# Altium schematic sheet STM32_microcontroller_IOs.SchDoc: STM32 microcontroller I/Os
size A4; Date: Not used; ApprovedBy: Not used; CheckedBy: Not used; Author: Not used; CompanyName: STMicroelectronics; DrawnBy: Not used; Engineer: Not used; Organization: Not used; Address1: Not used; Address2: Not used; Address3: Not used; Address4: Not used; DocumentNumber: 3; Revision: Not used; SheetNumber: 3; SheetTotal: 8
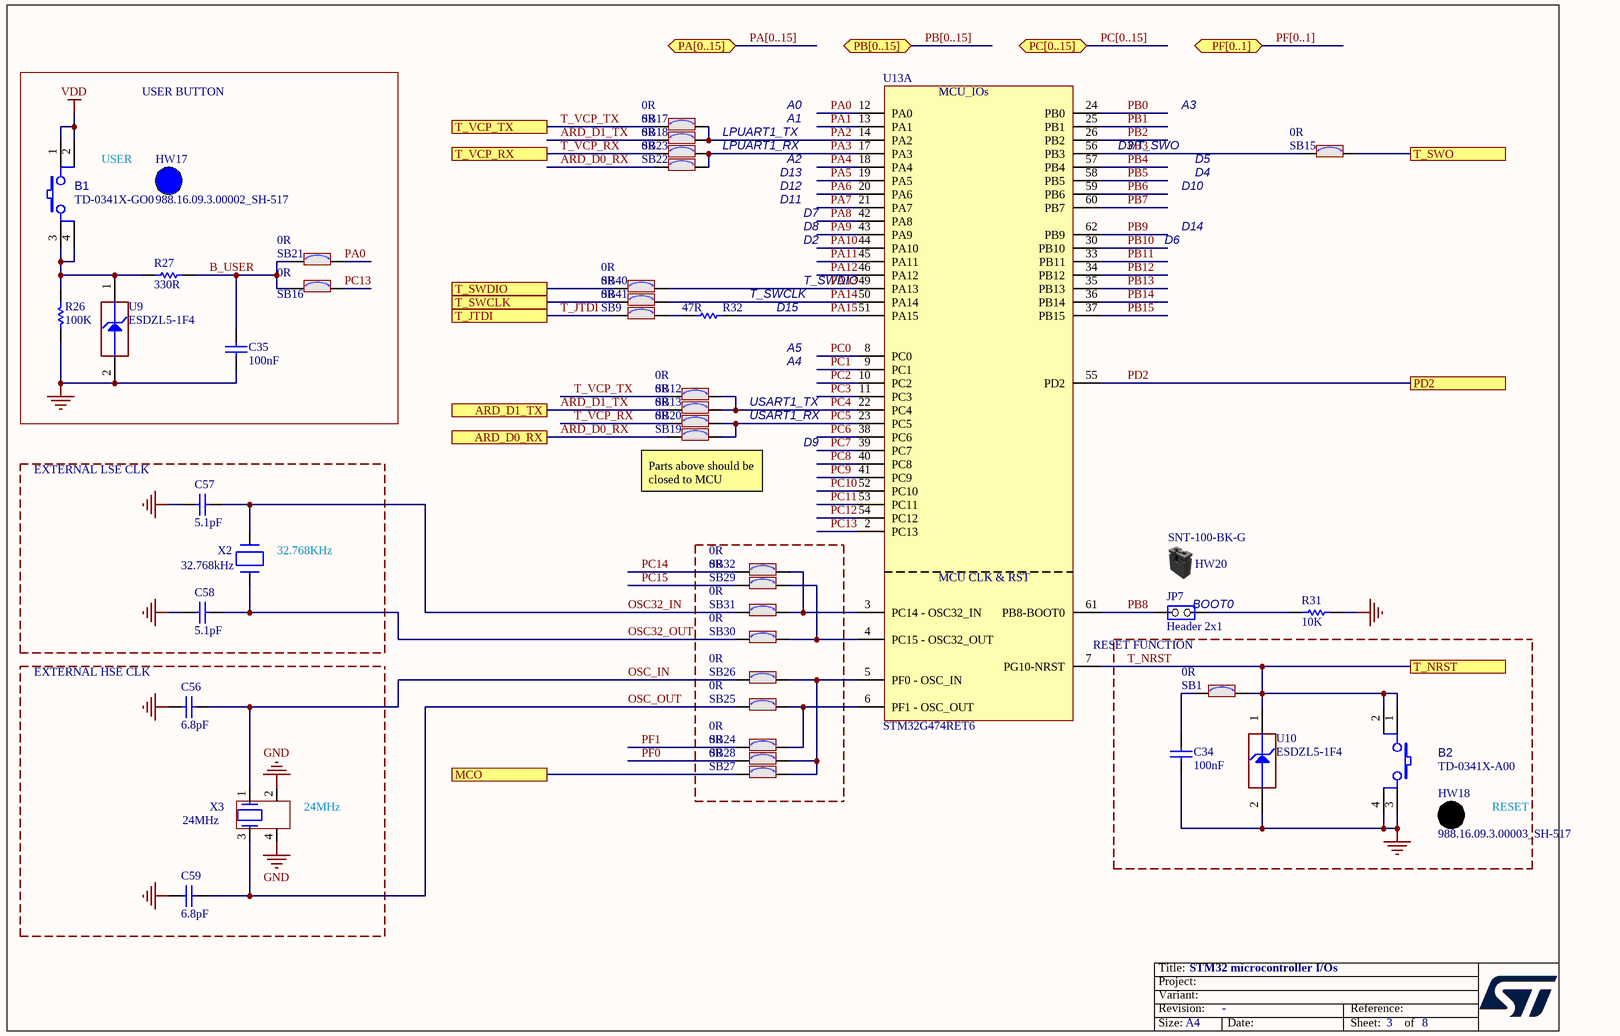
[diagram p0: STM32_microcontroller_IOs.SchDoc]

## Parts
B1  value TD-0341X-GO0  [SWI_WEALTHMETAL_TD-0341_4P_BLUE]
B2  value TD-0341X-A00  [SWI_WEALTHMETAL_TD-0341_4P_BLACK]
C34  value 100nF  [C0402]  (hidden comment: Capacitor)
C35  value 100nF  [C0402]  (hidden comment: Capacitor)
C56  value 6.8pF  [C0402]
C57  value 5.1pF  [C0402]
C58  value 5.1pF  [C0402]
C59  value 6.8pF  [C0402]
HW17  value 988.16.09.3.00002_SH-517  (mechanical)
HW18  value 988.16.09.3.00003_SH-517  (mechanical)
HW20  value SNT-100-BK-G  (mechanical)
JP7  value Header 2x1  [CON_SAMTEC_TSW-102-07-G-S]
R26  value 100K  [R0603]
R27  value 330R  [R0603]
R31  value 10K  [R0603]
R32  value 47R  [R0402]
SB1  value 0R  [SOLDER-BRIDGE_R0603-0R]
SB9  value 0R  [SOLDER-BRIDGE_R0603-0R]
SB12  value 0R  [SOLDER-BRIDGE_R0603-0R]
SB13  value 0R  [SOLDER-BRIDGE_R0603-0R]
SB15  value 0R  [SOLDER-BRIDGE_R0603-0R]
SB16  value 0R  [SOLDER-BRIDGE_R0603-0R]
SB17  value 0R  [SOLDER-BRIDGE_R0603-0R]
SB18  value 0R  [SOLDER-BRIDGE_R0603-0R]
SB19  value 0R  [SOLDER-BRIDGE_R0603-0R]
SB20  value 0R  [SOLDER-BRIDGE_R0603-0R]
SB21  value 0R  [SOLDER-BRIDGE_R0603-0R]
SB22  value 0R  [SOLDER-BRIDGE_R0603-0R]
SB23  value 0R  [SOLDER-BRIDGE_R0603-0R]
SB24  value 0R  [SOLDER-BRIDGE_R0603-0R]
SB25  value 0R  [SOLDER-BRIDGE_R0603-0R]
SB26  value 0R  [SOLDER-BRIDGE_R0603-0R]
SB27  value 0R  [SOLDER-BRIDGE_R0603-0R]
SB28  value 0R  [SOLDER-BRIDGE_R0603-0R]
SB29  value 0R  [SOLDER-BRIDGE_R0603-0R]
SB30  value 0R  [SOLDER-BRIDGE_R0603-0R]
SB31  value 0R  [SOLDER-BRIDGE_R0603-0R]
SB32  value 0R  [SOLDER-BRIDGE_R0603-0R]
SB40  value 0R  [SOLDER-BRIDGE_R0603-0R]
SB41  value 0R  [SOLDER-BRIDGE_R0603-0R]
U9  value ESDZL5-1F4  [ESD_0201_H0P3_1K_2A]  (hidden comment: ESD-TRANSIL)
U10  value ESDZL5-1F4  [ESD_0201_H0P3_1K_2A]  (hidden comment: ESD-TRANSIL)
U13  value STM32G474RET6  [ICC_LQFP64_10X10_P050_SOCKET_YAMAICHI_IC149-064-069-B5_NM]  (part A of 2)
X2  value 32.768kHz  [CRY_NX3215SA_2P]
X3  value 24MHz  [CRY_NX2016SA_4P]

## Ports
ARD_D0_RX, ARD_D1_TX, MCO, PA[0..15] (bidir), PB[0..15] (bidir), PC[0..15] (bidir), PD2, PF[0..1] (bidir), T_JTDI, T_NRST, T_SWCLK, T_SWDIO, T_SWO, T_VCP_RX, T_VCP_TX

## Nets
GND: B2.3 B2.4 C34.1 C35.1 C56.1 C57.2 C58.2 C59.1 R26.1 R31.1 U9.2(GND) U10.2(GND) X3.2 X3.4
VDD: B1.1 B1.2
ARD_D0_RX: SB19.2 SB22.2 ; port ARD_D0_RX
ARD_D1_TX: SB13.2 SB18.2 ; port ARD_D1_TX
B_USER: C35.2 R27.2 SB16.1 SB21.1
MCO: SB27.1 ; port MCO
OSC32_IN: C57.1 SB31.1 X2.1(X1)
OSC32_OUT: C58.1 SB30.1 X2.2(X2)
OSC_IN: C56.2 SB26.1 X3.1
OSC_OUT: C59.2 SB25.1 X3.3
PA0: SB21.2 U13.12(PA0)
PA1: U13.13(PA1)
PA2: SB17.2 SB18.1 U13.14(PA2)
PA3: SB22.1 SB23.2 U13.17(PA3)
PA4: U13.18(PA4)
PA5: U13.19(PA5)
PA6: U13.20(PA6)
PA7: U13.21(PA7)
PA8: U13.42(PA8)
PA9: U13.43(PA9)
PA10: U13.44(PA10)
PA11: U13.45(PA11)
PA12: U13.46(PA12)
PA13: SB40.2 U13.49(PA13)
PA14: SB41.2 U13.50(PA14)
PA15: R32.2 U13.51(PA15)
PB0: U13.24(PB0)
PB1: U13.25(PB1)
PB2: U13.26(PB2)
PB3: SB15.1 U13.56(PB3)
PB4: U13.57(PB4)
PB5: U13.58(PB5)
PB6: U13.59(PB6)
PB7: U13.60(PB7)
PB8: JP7.1(COMMON) U13.61(PB8-BOOT0)
PB9: U13.62(PB9)
PB10: U13.30(PB10)
PB11: U13.33(PB11)
PB12: U13.34(PB12)
PB13: U13.35(PB13)
PB14: U13.36(PB14)
PB15: U13.37(PB15)
PC0: U13.8(PC0)
PC1: U13.9(PC1)
PC2: U13.10(PC2)
PC3: U13.11(PC3)
PC4: SB12.2 SB13.1 U13.22(PC4)
PC5: SB19.1 SB20.2 U13.23(PC5)
PC6: U13.38(PC6)
PC7: U13.39(PC7)
PC8: U13.40(PC8)
PC9: U13.41(PC9)
PC10: U13.52(PC10)
PC11: U13.53(PC11)
PC12: U13.54(PC12)
PC13: SB16.2 U13.2(PC13)
PC14: SB32.1
PC15: SB29.1
PD2: U13.55(PD2) ; port PD2
PF0: SB28.1
PF1: SB24.1
T_JTDI: SB9.1 ; port T_JTDI
T_NRST: B2.1 B2.2 SB1.2 U10.1(IO1) U13.7(PG10-NRST) ; port T_NRST
T_SWCLK: SB41.1 ; port T_SWCLK
T_SWDIO: SB40.1 ; port T_SWDIO
T_SWO: SB15.2 ; port T_SWO
T_VCP_RX: SB20.1 SB23.1 ; port T_VCP_RX
T_VCP_TX: SB12.1 SB17.1 ; port T_VCP_TX
NetB1_3: B1.3 B1.4 R26.2 R27.1 U9.1(IO1)
NetC34_2: C34.2 SB1.1
NetJP7_2: JP7.2(NO) R31.2
NetR32_1: R32.1 SB9.2
NetSB24_2: SB24.2 SB25.2 U13.6(PF1_-_OSC_OUT)
NetSB26_2: SB26.2 SB27.2 SB28.2 U13.5(PF0_-_OSC_IN)
NetSB29_2: SB29.2 SB30.2 U13.4(PC15_-_OSC32_OUT)
NetSB31_2: SB31.2 SB32.2 U13.3(PC14_-_OSC32_IN)

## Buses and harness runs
bus PA[0..15] = port PA[0..15]
bus PB[0..15] = port PB[0..15]
bus PC[0..15] = port PC[0..15]
bus PF[0..1] = port PF[0..1]

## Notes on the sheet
- USER BUTTON
- A0
- A3
- USER
- LPUART1_TX
- LPUART1_RX
- A1
- A2
- D13
- D3/T_SWO
- D4
- D5
- D12
- D11
- D2
- D7
- D8
- D14
- D10
- D6
- (near R32) T_SWCLK
- D15
- (near R32) T_SWDIO
- A4
- A5
- USART1_RX
- USART1_TX
- D9
- EXTERNAL LSE CLK
- (near SB19) Parts above should be closed to MCU
- (near X2) 32.768KHz
- RESET FUNCTION
- BOOT0
- EXTERNAL HSE CLK
- (near X3) 24MHz
- RESET

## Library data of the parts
B1 = MCD-00002: Non-Open Push-Button 0.1A 24V; Manufacturer: WEALTHMETAL; Part_Type: Misc; Part_Preference: Forbidden; Partial_Alternate_Internal_Part_Number: MCD-03589; Provided_By: SUBCO; Alternate_EMS: A; Component_Country_Of_Origin: Unknown; ID: 2464; ShowFields: YES
B2 = MCD-00001: Non-Open Push-Button 0.1A 24V BLACK; Manufacturer: WEALTHMETAL; Part_Type: Misc; Part_Preference: Forbidden; Partial_Alternate_Internal_Part_Number: MCD-03587; Provided_By: SUBCO; Alternate_EMS: A; Component_Country_Of_Origin: Unknown; ID: 2463; ShowFields: YES
C34 C35 = MCD-00006: Capacitor, MLCC, 100nF, 16V, X7R, +/-10%, 0402, T=0.5mm; Manufacturer_Part_Number: CC0402KRX7R7BB104; Manufacturer: YAGEO; Part_Preference: Recommended; Partial_Alternate_Internal_Part_Number: MCD-03299; Order_Code_RS: 9402047; Component_Country_Of_Origin: China; ShowFields: YES; ID: 2474
C56 C59 = MCD-00674: Capacitor, MLCC, 6.8pF, 50V, NPO, +-0.25pF, 0402, T=0.5mm; Manufacturer_Part_Number: CC0402CRNPO9BN6R8; Manufacturer: YAGEO; Part_Preference: Recommended; Provided_By: SUBCO; Component_Country_Of_Origin: China; ID: 3068; ShowFields: YES
C57 C58 = MCD-00003: Capacitor, MLCC, 5.1pF, 50V, NPO, +-0.25pF, 0402, T=0.5mm; Manufacturer_Part_Number: CC0402CRNPO9BN5R1; Manufacturer: YAGEO; Part_Preference: Recommended; ECCN_US: EAR99; ECCN_EU: NEC; Provided_By: SUBCO; Component_Country_Of_Origin: China; ID: 2477; ShowFields: YES
HW17 = MCD-00634: Blue Hat for switch TD0341X-G01-BLU; Part_Type: Mechanical; Manufacturer: _A_JIUBABA; Part_Preference: Alternate; Provided_By: SUBCO; Alternate_EMS: A; Component_Country_Of_Origin: Unknown; ID: 3112; ShowFields: YES
HW18 = MCD-00635: Black Hat for switch TD0341X-G01-BLA; Part_Type: Mechanical; Manufacturer: _A_JIUBABA; Part_Preference: Alternate; Partial_Alternate_Internal_Part_Number: MCD-04574; Provided_By: SUBCO; Alternate_EMS: A; Component_Country_Of_Origin: Unknown; ID: 3106; ShowFields: YES
HW20 = MCD-00043: SHUNT 2.54mm BLACK; Manufacturer: SAMTEC; Part_Type: Misc; Manufacturer_HQ_COO: Unknown; Part_Preference: Recommended; Partial_Alternate_Internal_Part_Number: MCD-01849, MCD-01864, MCD-02388, MCD-03991, MCD-04284, MCD-04580; Provided_By: Subcon; Initial_Board_Reference: MB1274; Alternate_EMS: A; Component_Country_Of_Origin: China, Costa Rica, Malaysia, USA, Vietnam; ID: 2551; Order_Code_RS: 158-7784; ShowFields: YES
JP7 = MCD-00045: Header, 2x1, 2,54mm, VR, TH, Height 5.84mm/2.54mm; Part_Type: Connector; Manufacturer_Part_Number: TSW-102-07-G-S; Manufacturer: SAMTEC; Part_Preference: Recommended; Partial_Alternate_Internal_Part_Number: MCD-02389, MCD-02957, MCD-03720, MCD-03979, MCD-04249; Provided_By: Subcon; Initial_Board_Reference: MB1274; Component_Country_Of_Origin: China, Costa Rica, Malaysia, USA, Vietnam; ID: 2545; Order_Code_RS: 2505044; ShowFields: YES
R26 = MCD-00223: Resistor,100K,0603,1%,1/10W; Manufacturer_Part_Number: RC0603FR-07100KL; Manufacturer: YAGEO; Part_Preference: Recommended; Provided_By: Subcon; Initial_Board_Reference: MB1319; Component_Country_Of_Origin: China; ID: 2647; ShowFields: YES
R27 = MCD-00197: Resistor,330R,0603,1%,1/10W; Manufacturer_Part_Number: RC0603FR-07330RL; Manufacturer: YAGEO; BMS_Part_Number: 9129729; Part_Preference: Recommended; Provided_By: Subcon; Component_Country_Of_Origin: China; ID: 2672; ShowFields: YES
R31 = MCD-00220: Resistor,10K,0603,1%,1/10W; Manufacturer_Part_Number: RC0603FR-0710KL; Manufacturer: YAGEO; Part_Preference: Recommended; Provided_By: Subcon; Initial_Board_Reference: MB1319; Component_Country_Of_Origin: China; ID: 2649; ShowFields: YES
R32 = MCD-00481: Resistor,47R,0402,1%,1/16W; Manufacturer_Part_Number: RC0402FR-0747RL; Manufacturer: YAGEO; Part_Preference: Recommended; Provided_By: SUBCO; ECCN_US: EAR99; ECCN_EU: NEC; Component_Country_Of_Origin: China; ID: 2796; ShowFields: YES
SB1 SB9 SB12 SB13 SB15-SB32 SB40 SB41 = MCD-00071: Solder Bridge ON; Part_Type: Resistor; Manufacturer_Part_Number: RC0603JR-070RL; Manufacturer: YAGEO; Manufacturer_HQ_COO: Unknown; Part_Preference: Recommended; Provided_By: SUBCO; Component_Country_Of_Origin: China; ID: 2521; Order_Code_RS: 199-5647; ShowFields: YES
U9 U10 = MCD-03501: Diode, ESD TVS, 5V5, 100nA, 10V, 0201; Manufacturer: STMICROELECTRONICS; Part_Preference: Recommended; Component_Country_Of_Origin: Singapore; ID: 5617; ShowFields: YES
U13 = MCD-01243: STM32G474, LQFP64 package,  3D IC footprint with 2D socket footprint.; Manufacturer: STMICROELECTRONICS; BMS_Part_Number: 9175326; Manufacturer_HQ_COO: EU; Part_Preference: Recommended; Provided_By: SUBCO with ST control; ECCN_US: 3A991A2; ECCN_EU: NEC; Component_Country_Of_Origin: China; ID: 3257; Order_Code_RS: 193-9861; ShowFields: YES
X2 = MCD-00091: Crystal 32.768kHz, 6pF, +-20ppm, 50Kohms max, SMD; Manufacturer_Part_Number: NX3215SA-32.768KHz-EXS00A-MU00525; Manufacturer: NDK; Part_Type: Crystal_Osc; BMS_Part_Number: 9157034; Part_Preference: Recommended; ECCN_US: EAR99; ECCN_EU: NEC; Provided_By: SUBCO; Component_Country_Of_Origin: Japan; ID: 2553; ShowFields: YES
X3 = MCD-01036: Crystal 24MHz, 6pF, +-20ppm, 80ohms max, SMD; Part_Type: Crystal_Osc; Manufacturer_Part_Number: NX2016SA-24MHz-EXS00A-CS10820; Manufacturer: NDK; BMS_Part_Number: 9157045; Part_Preference: Recommended; ECCN_US: EAR99; ECCN_EU: NEC; Provided_By: SUBCO; Component_Country_Of_Origin: Japan; ID: 2989; ShowFields: YES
